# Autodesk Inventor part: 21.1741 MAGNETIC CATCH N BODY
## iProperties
Created: 2007-03
Part Number: 21.1741 MAGNETIC CATCH N BODY
Document SubType Name: Modeling
Designer: Andy Moles
Material: ABS Plastic
Mass: 14.6918 g
Surface Area: 52.4829 cm^2
Volume: 13.8602 cm^3
Density: 1.06 g/cm^3
Author: Andy Moles
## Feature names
1. Base1
